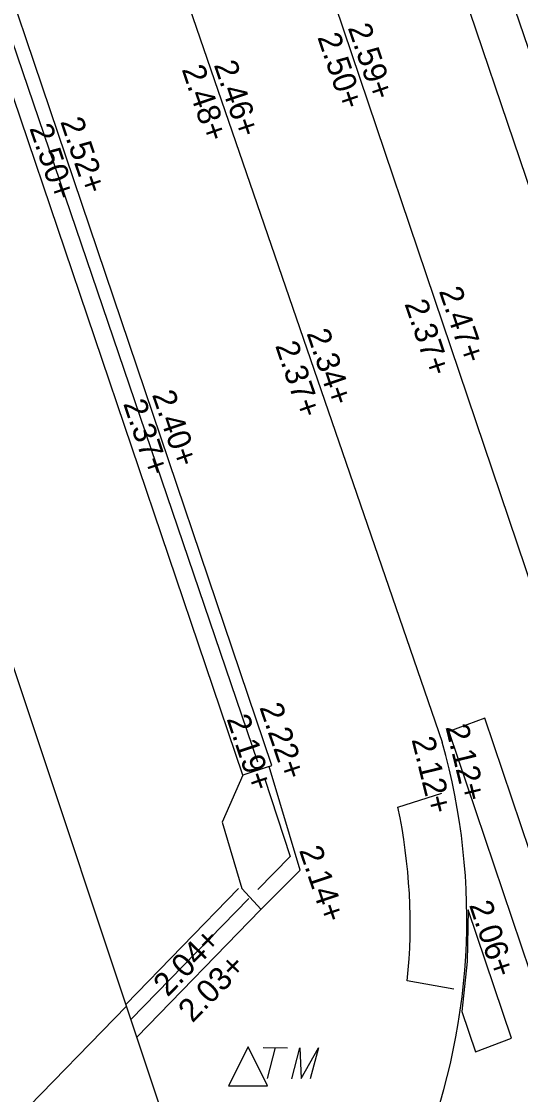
# Model space of a CAD drawing. Extents: x 122462 to 123306, y 485548 to 486417.
# Drawn here: x 122832.7 to 122839.17, y 486070.8 to 486084.73 of the extents above; entities that cross this region are included whole.
import ezdxf

# ---------------------------------------------------------------- set-up
doc = ezdxf.new("R2010")
doc.units = 0
for name, color, linetype in [('B-WE-AL-WERKGRENS-G', 7, 'Continuous'), ('B-WE-IE-TERREINAFSCHEIDING_KUNSTMATIG_HEKWERK-G', 7, 'Continuous'), ('B-WE-OG-HOOGTEPUNT-S', 7, 'Continuous'), ('B-WE-OG-TOPOGRAFIE_MUUR-G', 7, 'Continuous'), ('B-WE-OG-TOPOGRAFIE_RAILS-G', 7, 'Continuous'), ('B-WE-VH-KANTOPSLUITING_TROTTOIRBAND_130 150-G', 7, 'Continuous'), ('B-WE-VH-MATERIAALGRENS-G', 7, 'Continuous'), ('B-WE-VW-MARKERING_DWARS_OVERSTEEK_VOETGANGERS-G', 7, 'Continuous'), ('Level 14', 7, 'Continuous'), ('V meubilair trammast', 7, 'Continuous'), ('V-WE-GR-BOOM-S', 7, 'Continuous')]:
    doc.layers.add(name, color=color, linetype=linetype)

msp = doc.modelspace()

# ---------------------------------------------------------------- linework, layer by layer
at = {"layer": 'B-WE-AL-WERKGRENS-G'}
msp.add_lwpolyline([(122857.632, 486078.279), (122830.484, 486160.606), (122900.937, 486183.81), (122887.855, 486222.555), (122665.445, 486149.273), (122678.196, 486110.449), (122807.072, 486152.895), (122835.324, 486068.154)], dxfattribs=at)
at = {"layer": 'B-WE-IE-TERREINAFSCHEIDING_KUNSTMATIG_HEKWERK-G'}
for points in [[(122827.167, 486100.384), (122835.76, 486075.119)], [(122835.849, 486074.908), (122836.184, 486073.889), (122835.764, 486073.461)], [(122835.647, 486073.343), (122834.117, 486071.772)]]:
    msp.add_lwpolyline(points, dxfattribs=at)
at = {"layer": 'B-WE-OG-TOPOGRAFIE_MUUR-G'}
for points in [[(122835.911, 486075.06), (122835.947, 486075.072), (122831.626, 486087.852), (122827.266, 486100.764), (122827.168, 486100.731)], [(122835.568, 486074.944), (122831.247, 486087.724), (122826.887, 486100.636)], [(122835.8, 486073.198), (122836.313, 486073.712), (122835.911, 486075.06), (122835.568, 486074.944), (122835.302, 486074.336), (122835.557, 486073.474), (122835.805, 486073.202)], [(122834.052, 486071.969), (122835.513, 486073.476)], [(122834.194, 486071.542), (122835.8, 486073.198)]]:
    msp.add_lwpolyline(points, dxfattribs=at)
at = {"layer": 'B-WE-OG-TOPOGRAFIE_RAILS-G'}
msp.add_line((122832.11, 486105.5), (122839.825, 486082.745), dxfattribs=at)
at = {"layer": 'B-WE-VH-KANTOPSLUITING_TROTTOIRBAND_130 150-G'}
msp.add_arc((122830.096, 486073.078), 8.377, 337.415, 15.8936, dxfattribs=at)
at = {"layer": 'B-WE-VH-MATERIAALGRENS-G'}
for points in [[(122837.579, 486074.529), (122838.15, 486074.711)], [(122838.304, 486072.168), (122837.701, 486072.277)]]:
    msp.add_lwpolyline(points, dxfattribs=at)
msp.add_arc((122830.441, 486073.013), 7.298, 354.2117, 11.9901, dxfattribs=at)
at = {"layer": 'B-WE-VW-MARKERING_DWARS_OVERSTEEK_VOETGANGERS-G'}
msp.add_lwpolyline([(122839.992, 486071.877), (122838.708, 486075.686), (122838.239, 486075.512), (122839.523, 486071.703)], close=True, dxfattribs=at)
for points in [[(122838.491, 486073.199), (122838.477, 486072.526), (122838.409, 486071.877)], [(122838.409, 486071.877), (122838.585, 486071.355), (122839.054, 486071.529), (122838.491, 486073.199)]]:
    msp.add_lwpolyline(points, dxfattribs=at)
at = {"layer": 'Level 14'}
msp.add_line((122834.059, 486071.948), (122832.534, 486070.377), dxfattribs=at)
at = {"layer": 'V meubilair trammast'}
for p, q in [((122835.637, 486071.418), (122835.382, 486070.912)), ((122835.89, 486070.912), (122835.637, 486071.418)), ((122835.832, 486071.408), (122836.149, 486071.407)), ((122835.99, 486071.408), (122835.883, 486071.005)), ((122836.203, 486071.004), (122836.31, 486071.407)), ((122836.31, 486071.407), (122836.324, 486071.005)), ((122836.324, 486071.005), (122836.552, 486071.407)), ((122836.552, 486071.407), (122836.444, 486071.004)), ((122835.382, 486070.912), (122835.89, 486070.912))]:
    msp.add_line(p, q, dxfattribs=at)
at = {"layer": 'V-WE-GR-BOOM-S'}
for points in [[(122839.772, 486076.05), (122830.973, 486102.107), (122827.132, 486113.429)], [(122831.584, 486105.321), (122832.323, 486103.149), (122836.246, 486091.538), (122841.344, 486076.501)], [(122829.02, 486102.127), (122834.782, 486085.189), (122838.152, 486075.372)]]:
    msp.add_lwpolyline(points, dxfattribs=at)

# ---------------------------------------------------------------- texts
at = {"layer": 'B-WE-OG-HOOGTEPUNT-S'}
for s, rotation, p in [('2.59+', 288.6589, (122836.928, 486084.651)), ('2.50+', 288.6589, (122836.533, 486084.528)), ('2.46+', 288.6589, (122835.191, 486084.169)), ('2.48+', 288.6589, (122834.774, 486084.111)), ('2.50+', 288.6589, (122832.799, 486083.347)), ('2.52+', 288.6589, (122833.199, 486083.432)), ('2.47+', 288.6589, (122838.109, 486081.232)), ('2.37+', 288.6589, (122837.663, 486081.067)), ('2.34+', 288.6589, (122836.393, 486080.684)), ('2.37+', 288.6589, (122835.986, 486080.524)), ('2.40+', 288.6589, (122834.389, 486079.887)), ('2.37+', 288.6589, (122834.015, 486079.77)), ('2.22+', 288.6795, (122835.782, 486075.827)), ('2.19+', 288.6795, (122835.356, 486075.677)), ('2.12+', 283.6996, (122838.195, 486075.571)), ('2.12+', 283.6996, (122837.756, 486075.409)), ('2.14+', 288.6795, (122836.296, 486073.971)), ('2.06+', 288.6589, (122838.5, 486073.26)), ('2.04+', 45.875, (122834.594, 486072.057)), ('2.03+', 45.875, (122834.916, 486071.72))]:
    msp.add_text(s, height=0.3, rotation=rotation, dxfattribs=at).set_placement(p)

doc.saveas('drawing.dxf')
